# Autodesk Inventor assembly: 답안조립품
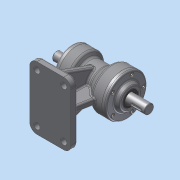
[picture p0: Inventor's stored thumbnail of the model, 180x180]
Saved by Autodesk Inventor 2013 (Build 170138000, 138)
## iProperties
Created: 2015-08
Part Number: 답안조립품
Document SubType Name: Assembly
Designer: Administrator
Author: Administrator
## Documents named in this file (10)
- C:\Users\Administrator\Desktop\450806V1020\답안조립품.iam
- C:\Users\Administrator\Desktop\450806V1020\본체.ipt
- C:\Users\Administrator\Desktop\450806V1020\M4x0.5.ipt
- C:\Users\Administrator\Desktop\450806V1020\뒤커버.ipt
- C:\Users\Administrator\Desktop\450806V1020\베어링 6203.ipt
- C:\Users\Administrator\Desktop\450806V1020\베어링 6205.ipt
- C:\Users\Administrator\Desktop\450806V1020\앞커버.ipt
- C:\Users\Administrator\Desktop\450806V1020\오일실 .ipt
- 오일실 .ipt
- C:\Users\Administrator\Desktop\450806V1020\축.ipt
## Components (10 placed, 1 different names)
1. M4x0.5:1
2. M4x0.5:2
3. M4x0.5:3
4. M4x0.5:4
5. M4x0.5:5
6. M4x0.5:6
7. M4x0.5:7
8. M4x0.5:8
9. M4x0.5:10
10. M4x0.5:11
